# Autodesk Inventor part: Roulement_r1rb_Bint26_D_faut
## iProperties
Created: 2011-10
Part Number: Roulement_r1rb_Bint26_D_faut
Document SubType Name: Modeling
Designer: Bruno
Author: Bruno
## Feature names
1. Base1
